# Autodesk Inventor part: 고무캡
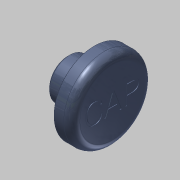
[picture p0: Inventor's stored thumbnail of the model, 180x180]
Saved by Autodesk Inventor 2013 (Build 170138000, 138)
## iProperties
Created: 2017-06
Part Number: 고무캡
Material: 고무
Document SubType Name: Modeling
Designer: mduedu
Density: 1 g/cm^3
Author: mduedu
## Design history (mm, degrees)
sketch "스케치1"
  geometry: L1 (0, 0)-(11, 0); L2 (11, 0)-(11, 10); L3 (11, 10)-(6.5, 10); L4 (0, 5)-(0, 0); L5 (0, 5)-(6, 5); L6 (6, 5)-(6, 9); L7 (6, 9)-(6.5, 9); L8 (6.5, 9)-(6.5, 10)
  constraints: 16 end point, 2 horizontal, 2 parallel, 2 perpendicular, 2 point on line, 1 vertical
  dimensions: "d0" = 20 diameter of L3 L1; "d2" = 10 diameter of L5 L1; "d6" = 5 distance between parallel lines of L2 L6; "d7" = 0.5 distance between parallel lines of L8 L6; "d8" = 18 diameter of L7 L1; "d9" = 6 distance between parallel lines of L6 L4
revolve "회전1" sketch "스케치1" stored, may be unused: angle "d10" = 90 deg
hole "구멍1" diameter "d22" = 7; stored, may be unused: countersink angle "d26" = 90 deg, drill point angle "d28" = 0 deg; dims "d23" = 6, "d24" = 4, "d25" = 2, "d27" = 6, "d32" = 10, "d33" = 10
chamfer "모따기1" distance "d13" = 0.5; stored, may be unused: second distance "d14" = 2, angle "d15" = 45 deg
fillet "모깎기3" dims "d29" = 1
fillet "모깎기1" dims "d16" = 0.1
fillet "모깎기2" dims "d17" = 2
sketch "스케치3"
  geometry: 2 further points
  constraints: 1 coincident, 1 other
feature "엠보싱1" sketch "스케치3" dims "d18" = 0.2, "d19" = 0
node "솔리드1"
